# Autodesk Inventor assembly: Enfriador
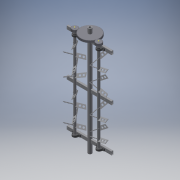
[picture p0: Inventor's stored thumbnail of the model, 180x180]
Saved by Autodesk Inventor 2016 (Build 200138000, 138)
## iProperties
Created: 2016-10
Part Number: Enfriador
Document SubType Name: Assembly
Designer: Ingenieria
Author: Ingenieria
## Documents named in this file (4)
- C:\Users\ingenieria\Desktop\Project\Enfriador.iam
- C:\Users\ingenieria\Desktop\Project\soporte_satelites.iam
- C:\Users\ingenieria\Desktop\Project\satelite_con_soporte.iam
- C:\Users\ingenieria\Desktop\Project\Enfriador\Design Accelerator\Spur Gears1.iam
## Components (4 placed, 3 different names)
1. soporte_satelites:1 [sub-assembly] — Mate:1, Angle:3, Mate:3, Mate:6, Tangent:1, Mate:8, Tangent:2
2. satelite_con_soporte:1 [sub-assembly] — Mate:6, Tangent:1, Mate:10, Rotation:1
3. satelite_con_soporte:2 [sub-assembly] — Mate:7, Mate:8, Tangent:2, Flush:1, Rotation:2
4. Spur Gears:1 [sub-assembly] — Mate:9, Flush:1, Rotation:1, Rotation:2
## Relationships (13: Mate 7, Tangent 2, RelateRotation 2, Angle 1, Flush 1)
- Mate:1: soporte_satelites:1
- Angle:3: soporte_satelites:1
- Mate:3: soporte_satelites:1
- Mate:6: soporte_satelites:1 ↔ satelite_con_soporte:1
- Tangent:1: soporte_satelites:1 ↔ satelite_con_soporte:1
- Mate:7: satelite_con_soporte:2
- Mate:8: soporte_satelites:1 ↔ satelite_con_soporte:2
- Tangent:2: soporte_satelites:1 ↔ satelite_con_soporte:2
- Mate:9: Spur Gears:1
- Flush:1: satelite_con_soporte:2 ↔ Spur Gears:1
- Mate:10: satelite_con_soporte:1
- Rotation:1 [RelateRotation]: satelite_con_soporte:1 ↔ Spur Gears:1
- Rotation:2 [RelateRotation]: satelite_con_soporte:2 ↔ Spur Gears:1
